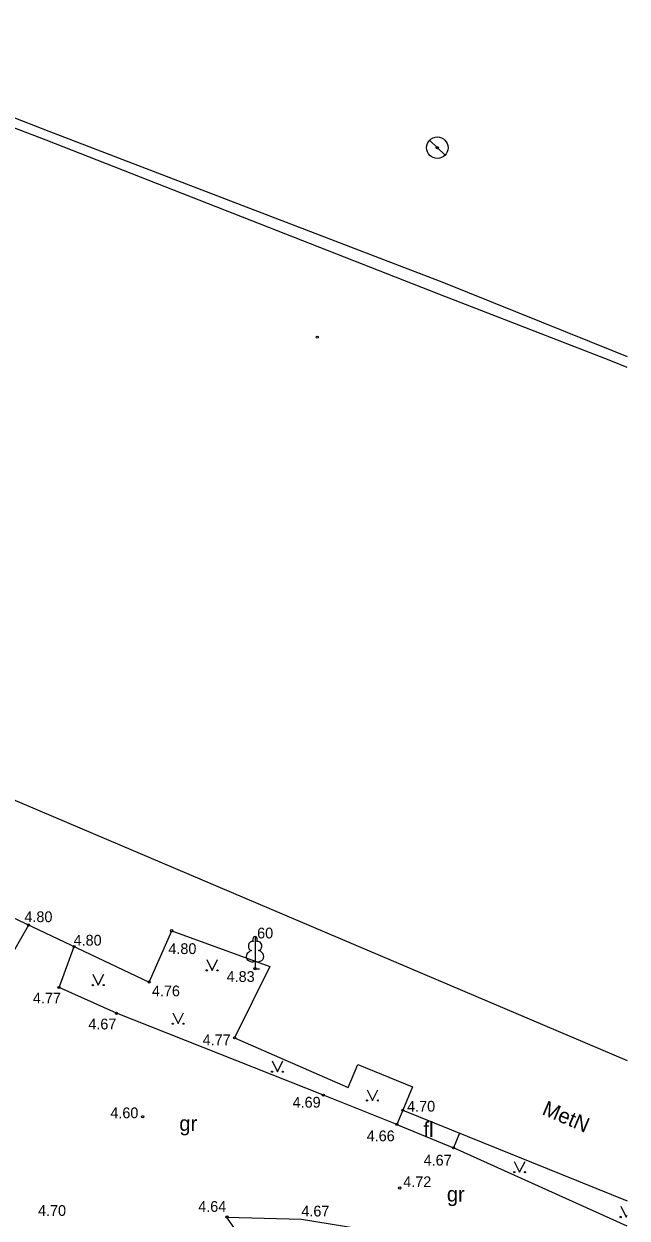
# Model space of a CAD drawing. Extents: x 484635 to 484808, y 278866 to 278977.
# Drawn here: x 484779.6 to 484807.6, y 278921.2 to 278976.7 of the extents above; entities that cross this region are included whole.
import ezdxf

# ---------------------------------------------------------------- set-up
doc = ezdxf.new("R2010")
doc.units = 0
for name, color, linetype in [('BUVE_EKAS_####_####_#', 7, 'Continuous'), ('BUVE_EKAS_BPAL_####_#', 7, 'Continuous'), ('BUVE_EKAS_RAKS_TKST_#', 7, 'Continuous'), ('CELI_CMAL_####_####_#', 7, 'Continuous'), ('CELI_CSEG_####_TKST_#', 7, 'Continuous'), ('CKOM_ELEM_####_####_#', 7, 'Continuous'), ('RELJ_AATZ_####_TKST_#', 7, 'Continuous'), ('RELJ_ELEM_####_####_#', 7, 'Continuous'), ('SILT_VADP_UDEN_####_#', 7, 'Continuous'), ('TERT_DIAM_####_TKST_#', 7, 'Continuous'), ('TERT_ELEM_####_####_#', 7, 'Continuous')]:
    doc.layers.add(name, color=color, linetype=linetype)

msp = doc.modelspace()

# ---------------------------------------------------------------- linework, layer by layer
at = {"layer": 'BUVE_EKAS_####_####_#'}
msp.add_line((484770.825, 278944.183), (484807.573, 278928.554), dxfattribs=at)
at = {"layer": 'BUVE_EKAS_BPAL_####_#'}
for points in [[(484776.87, 278936.215), (484785.374, 278932.197)], [(484785.374, 278932.197), (484786.419, 278934.585)], [(484785.374, 278932.197), (484786.419, 278934.585), (484790.979, 278932.919)], [(484790.979, 278932.919), (484789.339, 278929.604), (484794.621, 278927.297)], [(484794.621, 278927.297), (484795.063, 278928.368)], [(484795.063, 278928.368), (484797.6, 278927.322), (484797.156, 278926.244), (484807.573, 278922.027)]]:
    msp.add_lwpolyline(points, dxfattribs=at)
at = {"layer": 'CELI_CMAL_####_####_#'}
for p, q in [((484797.156, 278926.244), (484796.875, 278925.583)), ((484799.784, 278925.171), (484799.507, 278924.494))]:
    msp.add_line(p, q, dxfattribs=at)
for points in [[(484779.769, 278934.845), (484778.763, 278933.075), (484772.928, 278935.883), (484773.086, 278937.837)], [(484796.875, 278925.583), (484793.464, 278926.941), (484783.852, 278930.745), (484781.184, 278931.942), (484781.884, 278933.846)], [(484796.875, 278925.583), (484799.507, 278924.494)], [(484807.573, 278920.857), (484799.507, 278924.494)], [(484789.341, 278920.743), (484788.986, 278921.278), (484792.446, 278921.17), (484797.207, 278920.399), (484801.954, 278918.469), (484802.359, 278917.308), (484802.195, 278916.938)]]:
    msp.add_lwpolyline(points, dxfattribs=at)
at = {"layer": 'CKOM_ELEM_####_####_#'}
for p, q in [((484798.399, 278971.318), (484799.117, 278970.622)), ((484798.758, 278970.97), (484798.757, 278970.969))]:
    msp.add_line(p, q, dxfattribs=at)
msp.add_circle((484798.758, 278970.97), 0.5, dxfattribs=at)
at = {"layer": 'RELJ_ELEM_####_####_#'}
for centre in [(484798.758, 278970.97), (484793.181, 278962.167), (484779.769, 278934.845), (484786.419, 278934.585), (484781.884, 278933.846), (484790.291, 278932.816), (484785.374, 278932.197), (484781.184, 278931.942), (484783.852, 278930.745), (484789.339, 278929.604), (484793.464, 278926.941), (484785.072, 278925.937), (484797.156, 278926.244), (484796.875, 278925.583), (484799.507, 278924.494), (484797.01, 278922.625), (484788.986, 278921.278)]:
    msp.add_circle(centre, 0.05, dxfattribs=at)
at = {"layer": 'SILT_VADP_UDEN_####_#'}
for points in [[(484807.573, 278960.751), (484806.818, 278961.065), (484798.835, 278964.17), (484780.584, 278971.316), (484772.333, 278974.469), (484766.644, 278976.726)], [(484768.01, 278976.726), (484772.449, 278974.964), (484780.717, 278971.748), (484799.046, 278964.702), (484806.928, 278961.529), (484807.573, 278961.261)]]:
    msp.add_lwpolyline(points, dxfattribs=at)
at = {"layer": 'TERT_ELEM_####_####_#'}
for p, q in [((484788.047, 278933.239), (484788.297, 278932.739)), ((484788.297, 278932.739), (484788.547, 278933.239)), ((484790.291, 278933.163), (484790.291, 278932.816)), ((484782.758, 278932.556), (484783.008, 278932.056)), ((484783.008, 278932.056), (484783.258, 278932.556)), ((484790.291, 278932.816), (484790.491, 278932.816)), ((484786.469, 278930.764), (484786.719, 278930.264)), ((484786.719, 278930.264), (484786.969, 278930.764)), ((484791.081, 278928.532), (484791.331, 278928.032)), ((484791.331, 278928.032), (484791.581, 278928.532)), ((484795.492, 278927.19), (484795.742, 278926.69)), ((484795.742, 278926.69), (484795.992, 278927.19)), ((484802.331, 278923.86), (484802.581, 278923.36)), ((484802.581, 278923.36), (484802.831, 278923.86)), ((484807.277, 278921.774), (484807.527, 278921.274)), ((484807.527, 278921.274), (484807.573, 278921.367))]:
    msp.add_line(p, q, dxfattribs=at)
for points in [[(484790.291, 278934.316), (484790.291, 278933.163)], [(484790.38, 278934.084), (484790.379, 278934.085)]]:
    msp.add_lwpolyline(points, dxfattribs=at)
for centre, radius in [((484788.046, 278932.739), 0.028), ((484788.546, 278932.739), 0.0263), ((484782.758, 278932.056), 0.028), ((484783.258, 278932.056), 0.0263), ((484786.468, 278930.263), 0.028), ((484786.968, 278930.263), 0.0263), ((484791.081, 278928.031), 0.028), ((484791.581, 278928.031), 0.0263), ((484795.492, 278926.69), 0.028), ((484795.992, 278926.69), 0.0263), ((484802.331, 278923.36), 0.028), ((484802.831, 278923.36), 0.0263), ((484807.277, 278921.274), 0.028)]:
    msp.add_circle(centre, radius, dxfattribs=at)
for centre, major_axis, ratio, start_param, end_param in [((484790.291, 278934.166), (0, -0.15), 0.707107, 3.14537, 5.287485), ((484790.29, 278934.166), (0, -0.15), 0.707107, 0.995701, 3.137816), ((484790.162, 278933.872), (-0.039, -0.212), 0.861323, 3.141593, 6.283185), ((484790.419, 278933.872), (0.039, -0.212), 0.861323, 0, 3.141593), ((484790.201, 278933.409), (0.307, 0.095), 0.814445, 1.570796, 4.752015), ((484790.38, 278933.409), (-0.307, 0.095), 0.814445, 1.531171, 4.712389)]:
    msp.add_ellipse(centre, major_axis=major_axis, ratio=ratio, start_param=start_param, end_param=end_param, dxfattribs=at)

# ---------------------------------------------------------------- texts
at = {"layer": 'BUVE_EKAS_RAKS_TKST_#'}
msp.add_text('MetN', height=0.7, rotation=336.8447, dxfattribs=at).set_placement((484803.577, 278926.062))
at = {"layer": 'CELI_CSEG_####_TKST_#'}
for s, p in [('gr', (484786.772, 278925.28)), ('fl', (484798.115, 278925.002)), ('gr', (484799.201, 278921.993))]:
    msp.add_text(s, height=0.7, dxfattribs=at).set_placement(p)
at = {"layer": 'RELJ_AATZ_####_TKST_#'}
for s, p in [('4.80', (484779.577, 278934.982)), ('4.80', (484781.861, 278933.891)), ('4.80', (484786.265, 278933.499)), ('4.83', (484788.97, 278932.203)), ('4.76', (484785.499, 278931.534)), ('4.77', (484779.971, 278931.201)), ('4.67', (484782.546, 278929.996)), ('4.77', (484787.854, 278929.263)), ('4.69', (484792.035, 278926.36)), ('4.70', (484797.355, 278926.175)), ('4.60', (484783.568, 278925.869)), ('4.66', (484795.475, 278924.799)), ('4.67', (484798.121, 278923.67)), ('4.72', (484797.173, 278922.665)), ('4.64', (484787.651, 278921.518)), ('4.70', (484780.209, 278921.329)), ('4.67', (484792.442, 278921.303))]:
    msp.add_text(s, height=0.5, dxfattribs=at).set_placement(p)
at = {"layer": 'TERT_DIAM_####_TKST_#'}
msp.add_text('60', height=0.5, dxfattribs=at).set_placement((484790.388, 278934.225))

doc.saveas('drawing.dxf')
